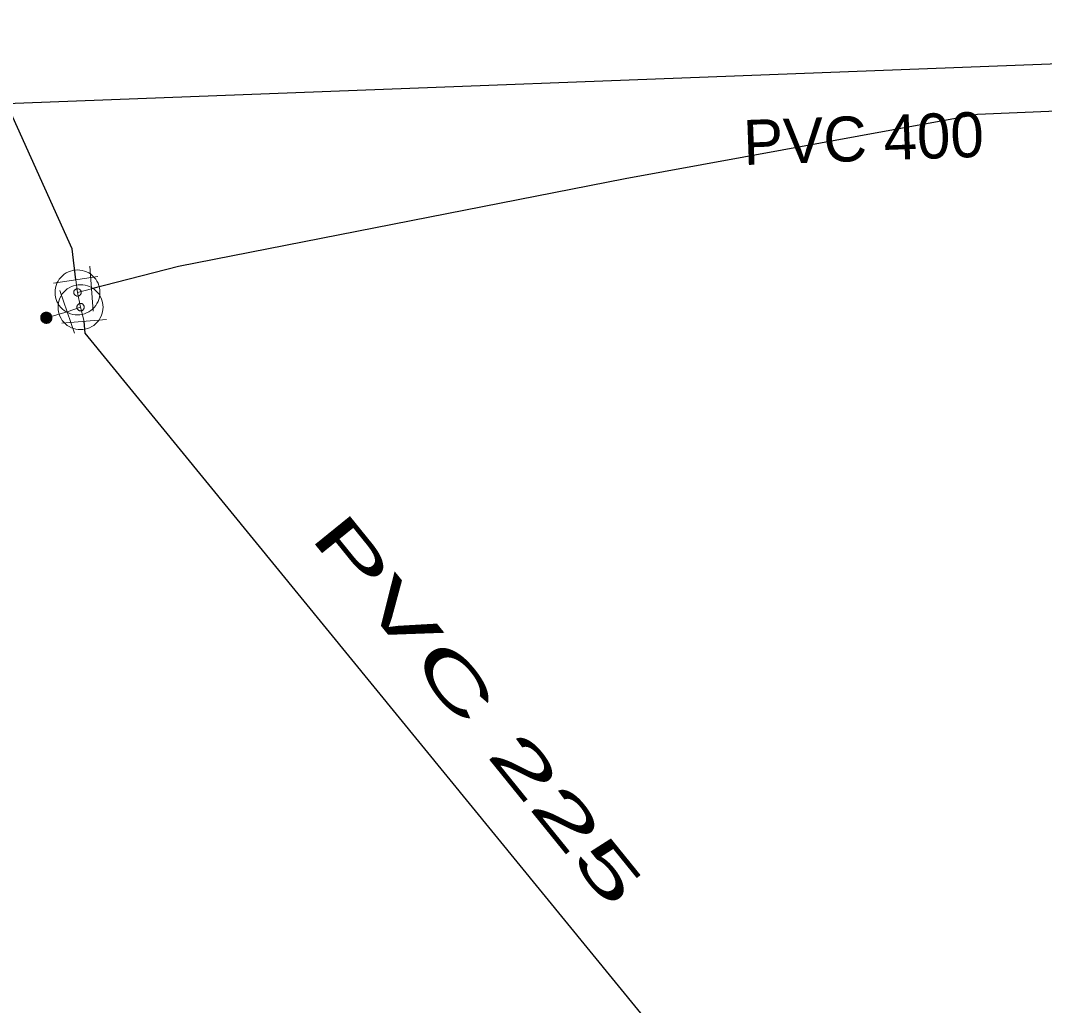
# Model space of a CAD drawing. Extents: x -659250 to -657316, y -997555 to -993684.
# Drawn here: x -658188.9 to -658166.14, y -996468.86 to -996446.96 of the extents above; entities that cross this region are included whole.
import ezdxf

# ---------------------------------------------------------------- set-up
doc = ezdxf.new("R2010")
doc.units = 0
doc.header["$LTSCALE"] = 0.4
doc.layers.add('1', color=7, linetype='Continuous')
for name, color, linetype, lineweight in [('14', 7, 'Continuous', 25), ('17', 7, 'Continuous', 25), ('34', 7, 'Continuous', 13), ('47', 7, 'Continuous', 13), ('9', 7, 'Continuous', 13)]:
    doc.layers.add(name, color=color, linetype=linetype, lineweight=lineweight)

msp = doc.modelspace()

# ---------------------------------------------------------------- linework, layer by layer
at = {"layer": '14'}
msp.add_line((-658148.079, -996447.25), (-658190.719, -996448.87), dxfattribs=at)
at = {"layer": '14', "lineweight": 13}
for p, q in [((-658187.636, -996453.006), (-658187.329, -996452.923)), ((-658187.866, -996453.436), (-658188.329, -996453.569)), ((-658187.57, -996453.333), (-658187.866, -996453.436)), ((-658187.489, -996453.649), (-658187.57, -996453.333))]:
    msp.add_line(p, q, dxfattribs=at)
msp.add_lwpolyline([(-658187.57, -996453.334), (-658187.637, -996453.006), (-658187.677, -996452.73)], dxfattribs=at)
at = {"layer": '17'}
for points in [[(-658187.677, -996452.73), (-658187.756, -996452.037), (-658193.366, -996439.601), (-658202.822, -996415.717), (-658204.513, -996411.723), (-658210.651, -996397.227), (-658216.25, -996384.063), (-658217.364, -996381.052), (-658220.46, -996373.316), (-658223.436, -996366.695), (-658223.489, -996366.02), (-658224.153, -996365.028), (-658230.886, -996355.498), (-658241.289, -996342), (-658242.23, -996340.93)], [(-658056.17, -996447.719), (-658057.34, -996448.37), (-658058.399, -996448.87), (-658072.379, -996455.03), (-658086.712, -996460.184), (-658096.55, -996463.013), (-658107.8, -996460.728), (-658119.059, -996456.26), (-658122.789, -996456.213), (-658137.155, -996451.888), (-658147.859, -996448.16), (-658148.32, -996447.94), (-658149.93, -996448.17), (-658151.399, -996448.37), (-658167.629, -996449.05), (-658175.464, -996450.478), (-658185.39, -996452.43), (-658187.329, -996452.923)], [(-658174.617, -996469.633), (-658187.469, -996453.91), (-658187.489, -996453.649)]]:
    msp.add_lwpolyline(points, dxfattribs=at)
at = {"layer": '34'}
for p, q in [((-658187.29, -996453.421), (-658187.366, -996452.424)), ((-658187.182, -996452.656), (-658188.171, -996452.802)), ((-658188.028, -996452.963), (-658187.704, -996453.909)), ((-658186.99, -996453.61), (-658187.987, -996453.686))]:
    msp.add_line(p, q, dxfattribs=at)
at = {"layer": '47'}
for points in [[(-658187.137, -996453.006), (-658187.14, -996452.954), (-658187.148, -996452.902), (-658187.162, -996452.852), (-658187.179, -996452.803), (-658187.204, -996452.756), (-658187.233, -996452.712), (-658187.266, -996452.672), (-658187.303, -996452.635), (-658187.343, -996452.602), (-658187.387, -996452.573), (-658187.434, -996452.549), (-658187.483, -996452.531), (-658187.532, -996452.517), (-658187.585, -996452.509), (-658187.637, -996452.506), (-658187.689, -996452.509), (-658187.741, -996452.517), (-658187.792, -996452.531), (-658187.84, -996452.549), (-658187.887, -996452.573), (-658187.931, -996452.602), (-658187.972, -996452.635), (-658188.009, -996452.672), (-658188.042, -996452.712), (-658188.07, -996452.756), (-658188.094, -996452.803), (-658188.113, -996452.852), (-658188.125, -996452.902), (-658188.134, -996452.954), (-658188.137, -996453.006), (-658188.134, -996453.058), (-658188.125, -996453.11), (-658188.113, -996453.161), (-658188.094, -996453.209), (-658188.07, -996453.256), (-658188.042, -996453.3), (-658188.009, -996453.341), (-658187.972, -996453.378), (-658187.931, -996453.411), (-658187.887, -996453.439), (-658187.84, -996453.463), (-658187.792, -996453.482), (-658187.741, -996453.495), (-658187.689, -996453.503), (-658187.637, -996453.506), (-658187.585, -996453.503), (-658187.532, -996453.495), (-658187.483, -996453.482), (-658187.434, -996453.463), (-658187.387, -996453.439), (-658187.343, -996453.411), (-658187.303, -996453.378), (-658187.266, -996453.341), (-658187.233, -996453.3), (-658187.204, -996453.256), (-658187.179, -996453.209), (-658187.162, -996453.161), (-658187.148, -996453.11), (-658187.14, -996453.058)], [(-658187.07, -996453.334), (-658187.073, -996453.282), (-658187.081, -996453.23), (-658187.095, -996453.18), (-658187.112, -996453.131), (-658187.137, -996453.084), (-658187.166, -996453.04), (-658187.198, -996453), (-658187.235, -996452.963), (-658187.276, -996452.93), (-658187.32, -996452.901), (-658187.367, -996452.877), (-658187.416, -996452.859), (-658187.465, -996452.845), (-658187.517, -996452.837), (-658187.57, -996452.834), (-658187.622, -996452.837), (-658187.674, -996452.845), (-658187.725, -996452.859), (-658187.772, -996452.877), (-658187.82, -996452.901), (-658187.864, -996452.93), (-658187.904, -996452.963), (-658187.941, -996453), (-658187.975, -996453.04), (-658188.002, -996453.084), (-658188.027, -996453.131), (-658188.046, -996453.18), (-658188.058, -996453.23), (-658188.066, -996453.282), (-658188.07, -996453.334), (-658188.066, -996453.386), (-658188.058, -996453.438), (-658188.046, -996453.489), (-658188.027, -996453.537), (-658188.002, -996453.584), (-658187.975, -996453.628), (-658187.941, -996453.669), (-658187.904, -996453.706), (-658187.864, -996453.739), (-658187.82, -996453.767), (-658187.772, -996453.791), (-658187.725, -996453.81), (-658187.674, -996453.823), (-658187.622, -996453.831), (-658187.57, -996453.834), (-658187.517, -996453.831), (-658187.465, -996453.823), (-658187.416, -996453.81), (-658187.367, -996453.791), (-658187.32, -996453.767), (-658187.276, -996453.739), (-658187.235, -996453.706), (-658187.198, -996453.669), (-658187.166, -996453.628), (-658187.137, -996453.584), (-658187.112, -996453.537), (-658187.095, -996453.489), (-658187.081, -996453.438), (-658187.073, -996453.386)], [(-658187.554, -996453.006), (-658187.554, -996452.997), (-658187.557, -996452.989), (-658187.559, -996452.981), (-658187.562, -996452.973), (-658187.566, -996452.965), (-658187.571, -996452.958), (-658187.576, -996452.951), (-658187.581, -996452.945), (-658187.589, -996452.94), (-658187.596, -996452.935), (-658187.603, -996452.931), (-658187.612, -996452.928), (-658187.62, -996452.926), (-658187.628, -996452.924), (-658187.637, -996452.924), (-658187.646, -996452.924), (-658187.654, -996452.926), (-658187.662, -996452.928), (-658187.67, -996452.931), (-658187.678, -996452.935), (-658187.684, -996452.94), (-658187.692, -996452.945), (-658187.698, -996452.951), (-658187.704, -996452.958), (-658187.708, -996452.965), (-658187.712, -996452.973), (-658187.715, -996452.981), (-658187.717, -996452.989), (-658187.719, -996452.997), (-658187.719, -996453.006), (-658187.719, -996453.015), (-658187.717, -996453.023), (-658187.715, -996453.031), (-658187.712, -996453.039), (-658187.708, -996453.047), (-658187.704, -996453.054), (-658187.698, -996453.061), (-658187.692, -996453.067), (-658187.684, -996453.073), (-658187.678, -996453.077), (-658187.67, -996453.081), (-658187.662, -996453.084), (-658187.654, -996453.086), (-658187.646, -996453.088), (-658187.637, -996453.088), (-658187.628, -996453.088), (-658187.62, -996453.086), (-658187.612, -996453.084), (-658187.603, -996453.081), (-658187.596, -996453.077), (-658187.589, -996453.073), (-658187.581, -996453.067), (-658187.576, -996453.061), (-658187.571, -996453.054), (-658187.566, -996453.047), (-658187.562, -996453.039), (-658187.559, -996453.031), (-658187.557, -996453.023), (-658187.554, -996453.015)], [(-658187.487, -996453.334), (-658187.487, -996453.325), (-658187.49, -996453.317), (-658187.492, -996453.309), (-658187.495, -996453.301), (-658187.499, -996453.293), (-658187.504, -996453.286), (-658187.509, -996453.279), (-658187.514, -996453.273), (-658187.522, -996453.268), (-658187.529, -996453.263), (-658187.536, -996453.259), (-658187.544, -996453.256), (-658187.553, -996453.254), (-658187.561, -996453.252), (-658187.57, -996453.252), (-658187.578, -996453.252), (-658187.587, -996453.254), (-658187.595, -996453.256), (-658187.603, -996453.259), (-658187.61, -996453.263), (-658187.617, -996453.268), (-658187.625, -996453.273), (-658187.63, -996453.279), (-658187.637, -996453.286), (-658187.641, -996453.293), (-658187.644, -996453.301), (-658187.647, -996453.309), (-658187.649, -996453.317), (-658187.652, -996453.325), (-658187.652, -996453.334), (-658187.652, -996453.343), (-658187.649, -996453.351), (-658187.647, -996453.359), (-658187.644, -996453.367), (-658187.641, -996453.375), (-658187.637, -996453.382), (-658187.63, -996453.389), (-658187.625, -996453.395), (-658187.617, -996453.401), (-658187.61, -996453.405), (-658187.603, -996453.409), (-658187.595, -996453.412), (-658187.587, -996453.414), (-658187.578, -996453.416), (-658187.57, -996453.416), (-658187.561, -996453.416), (-658187.553, -996453.414), (-658187.544, -996453.412), (-658187.536, -996453.409), (-658187.529, -996453.405), (-658187.522, -996453.401), (-658187.514, -996453.395), (-658187.509, -996453.389), (-658187.504, -996453.382), (-658187.499, -996453.375), (-658187.495, -996453.367), (-658187.492, -996453.359), (-658187.49, -996453.351), (-658187.487, -996453.343)]]:
    msp.add_lwpolyline(points, close=True, dxfattribs=at)
at = {"layer": '9'}
for points in [[(-658188.455, -996453.569), (-658188.455, -996453.582), (-658188.453, -996453.595), (-658188.45, -996453.608), (-658188.445, -996453.62), (-658188.439, -996453.632), (-658188.432, -996453.643), (-658188.424, -996453.653), (-658188.414, -996453.663), (-658188.404, -996453.671), (-658188.393, -996453.678), (-658188.381, -996453.684), (-658188.369, -996453.689), (-658188.356, -996453.692), (-658188.343, -996453.694), (-658188.33, -996453.696), (-658188.317, -996453.695), (-658188.304, -996453.693), (-658188.291, -996453.69), (-658188.279, -996453.685), (-658188.267, -996453.679), (-658188.256, -996453.672), (-658188.246, -996453.664), (-658188.236, -996453.654), (-658188.228, -996453.644), (-658188.221, -996453.633), (-658188.215, -996453.621), (-658188.21, -996453.609), (-658188.207, -996453.596), (-658188.205, -996453.583), (-658188.203, -996453.57), (-658188.204, -996453.557), (-658188.206, -996453.544), (-658188.209, -996453.531), (-658188.214, -996453.519), (-658188.22, -996453.507), (-658188.227, -996453.496), (-658188.235, -996453.486), (-658188.245, -996453.476), (-658188.255, -996453.468), (-658188.266, -996453.461), (-658188.278, -996453.455), (-658188.29, -996453.45), (-658188.303, -996453.447), (-658188.316, -996453.445), (-658188.329, -996453.444), (-658188.342, -996453.444), (-658188.355, -996453.446), (-658188.368, -996453.449), (-658188.38, -996453.454), (-658188.392, -996453.46), (-658188.403, -996453.467), (-658188.413, -996453.475), (-658188.423, -996453.485), (-658188.431, -996453.495), (-658188.438, -996453.506), (-658188.444, -996453.518), (-658188.449, -996453.53), (-658188.452, -996453.543), (-658188.454, -996453.556)], [(-658188.435, -996453.569), (-658188.436, -996453.58), (-658188.434, -996453.591), (-658188.431, -996453.602), (-658188.427, -996453.612), (-658188.422, -996453.622), (-658188.416, -996453.631), (-658188.409, -996453.64), (-658188.401, -996453.648), (-658188.392, -996453.655), (-658188.383, -996453.661), (-658188.373, -996453.666), (-658188.363, -996453.67), (-658188.352, -996453.673), (-658188.341, -996453.676), (-658188.33, -996453.676), (-658188.319, -996453.676), (-658188.308, -996453.674), (-658188.297, -996453.671), (-658188.287, -996453.667), (-658188.277, -996453.662), (-658188.268, -996453.656), (-658188.259, -996453.649), (-658188.251, -996453.641), (-658188.244, -996453.632), (-658188.238, -996453.623), (-658188.233, -996453.613), (-658188.229, -996453.603), (-658188.226, -996453.592), (-658188.224, -996453.581), (-658188.223, -996453.57), (-658188.223, -996453.559), (-658188.225, -996453.548), (-658188.228, -996453.537), (-658188.232, -996453.527), (-658188.237, -996453.517), (-658188.243, -996453.508), (-658188.25, -996453.499), (-658188.258, -996453.491), (-658188.267, -996453.484), (-658188.276, -996453.478), (-658188.286, -996453.473), (-658188.296, -996453.469), (-658188.307, -996453.466), (-658188.318, -996453.464), (-658188.329, -996453.464), (-658188.34, -996453.463), (-658188.351, -996453.465), (-658188.362, -996453.468), (-658188.372, -996453.472), (-658188.382, -996453.477), (-658188.391, -996453.483), (-658188.4, -996453.49), (-658188.408, -996453.498), (-658188.415, -996453.507), (-658188.421, -996453.516), (-658188.426, -996453.526), (-658188.43, -996453.536), (-658188.433, -996453.547), (-658188.435, -996453.558)], [(-658188.416, -996453.569), (-658188.416, -996453.578), (-658188.415, -996453.587), (-658188.412, -996453.596), (-658188.409, -996453.604), (-658188.405, -996453.612), (-658188.4, -996453.62), (-658188.394, -996453.627), (-658188.388, -996453.633), (-658188.381, -996453.639), (-658188.373, -996453.644), (-658188.365, -996453.648), (-658188.357, -996453.651), (-658188.348, -996453.654), (-658188.339, -996453.655), (-658188.33, -996453.657), (-658188.321, -996453.656), (-658188.312, -996453.655), (-658188.303, -996453.652), (-658188.295, -996453.649), (-658188.287, -996453.645), (-658188.279, -996453.64), (-658188.272, -996453.634), (-658188.266, -996453.628), (-658188.26, -996453.621), (-658188.255, -996453.613), (-658188.251, -996453.605), (-658188.248, -996453.597), (-658188.245, -996453.588), (-658188.244, -996453.579), (-658188.242, -996453.57), (-658188.243, -996453.561), (-658188.244, -996453.552), (-658188.247, -996453.543), (-658188.25, -996453.535), (-658188.254, -996453.527), (-658188.259, -996453.519), (-658188.265, -996453.512), (-658188.271, -996453.506), (-658188.278, -996453.5), (-658188.286, -996453.495), (-658188.294, -996453.491), (-658188.302, -996453.488), (-658188.311, -996453.485), (-658188.32, -996453.484), (-658188.329, -996453.483), (-658188.338, -996453.483), (-658188.347, -996453.484), (-658188.356, -996453.487), (-658188.364, -996453.49), (-658188.372, -996453.494), (-658188.38, -996453.499), (-658188.387, -996453.505), (-658188.393, -996453.511), (-658188.399, -996453.518), (-658188.404, -996453.526), (-658188.408, -996453.534), (-658188.411, -996453.542), (-658188.414, -996453.551), (-658188.415, -996453.56)], [(-658188.396, -996453.569), (-658188.396, -996453.576), (-658188.395, -996453.583), (-658188.394, -996453.59), (-658188.391, -996453.596), (-658188.388, -996453.602), (-658188.384, -996453.608), (-658188.38, -996453.614), (-658188.375, -996453.619), (-658188.369, -996453.623), (-658188.363, -996453.627), (-658188.357, -996453.63), (-658188.351, -996453.633), (-658188.344, -996453.634), (-658188.337, -996453.637), (-658188.33, -996453.637), (-658188.323, -996453.637), (-658188.316, -996453.635), (-658188.309, -996453.634), (-658188.303, -996453.631), (-658188.296, -996453.628), (-658188.291, -996453.624), (-658188.285, -996453.62), (-658188.28, -996453.615), (-658188.276, -996453.609), (-658188.272, -996453.603), (-658188.269, -996453.597), (-658188.266, -996453.591), (-658188.264, -996453.584), (-658188.263, -996453.577), (-658188.262, -996453.57), (-658188.262, -996453.563), (-658188.263, -996453.556), (-658188.265, -996453.549), (-658188.268, -996453.543), (-658188.271, -996453.536), (-658188.275, -996453.531), (-658188.279, -996453.525), (-658188.284, -996453.52), (-658188.29, -996453.516), (-658188.295, -996453.512), (-658188.302, -996453.509), (-658188.308, -996453.506), (-658188.315, -996453.504), (-658188.322, -996453.503), (-658188.329, -996453.503), (-658188.336, -996453.503), (-658188.343, -996453.503), (-658188.35, -996453.505), (-658188.356, -996453.508), (-658188.362, -996453.511), (-658188.368, -996453.515), (-658188.374, -996453.519), (-658188.379, -996453.524), (-658188.383, -996453.53), (-658188.387, -996453.535), (-658188.39, -996453.542), (-658188.393, -996453.548), (-658188.394, -996453.555), (-658188.396, -996453.562)], [(-658188.376, -996453.569), (-658188.376, -996453.574), (-658188.376, -996453.579), (-658188.375, -996453.584), (-658188.373, -996453.588), (-658188.371, -996453.593), (-658188.368, -996453.597), (-658188.365, -996453.6), (-658188.361, -996453.604), (-658188.358, -996453.607), (-658188.354, -996453.61), (-658188.349, -996453.612), (-658188.345, -996453.614), (-658188.34, -996453.615), (-658188.335, -996453.617), (-658188.33, -996453.617), (-658188.325, -996453.617), (-658188.32, -996453.616), (-658188.315, -996453.615), (-658188.311, -996453.613), (-658188.306, -996453.611), (-658188.302, -996453.608), (-658188.298, -996453.605), (-658188.295, -996453.601), (-658188.292, -996453.598), (-658188.289, -996453.594), (-658188.287, -996453.589), (-658188.285, -996453.585), (-658188.284, -996453.58), (-658188.283, -996453.575), (-658188.282, -996453.57), (-658188.282, -996453.565), (-658188.283, -996453.56), (-658188.284, -996453.555), (-658188.286, -996453.551), (-658188.288, -996453.546), (-658188.291, -996453.542), (-658188.294, -996453.538), (-658188.297, -996453.535), (-658188.301, -996453.532), (-658188.305, -996453.529), (-658188.31, -996453.527), (-658188.314, -996453.525), (-658188.319, -996453.524), (-658188.324, -996453.523), (-658188.329, -996453.523), (-658188.334, -996453.523), (-658188.339, -996453.524), (-658188.344, -996453.524), (-658188.348, -996453.526), (-658188.353, -996453.528), (-658188.357, -996453.531), (-658188.36, -996453.534), (-658188.364, -996453.537), (-658188.367, -996453.541), (-658188.37, -996453.545), (-658188.372, -996453.55), (-658188.374, -996453.554), (-658188.375, -996453.559), (-658188.376, -996453.564)], [(-658188.356, -996453.569), (-658188.356, -996453.572), (-658188.357, -996453.575), (-658188.356, -996453.577), (-658188.355, -996453.58), (-658188.354, -996453.583), (-658188.352, -996453.585), (-658188.35, -996453.587), (-658188.348, -996453.589), (-658188.346, -996453.591), (-658188.344, -996453.593), (-658188.341, -996453.595), (-658188.338, -996453.596), (-658188.336, -996453.596), (-658188.333, -996453.597), (-658188.33, -996453.597), (-658188.327, -996453.597), (-658188.324, -996453.597), (-658188.321, -996453.596), (-658188.319, -996453.595), (-658188.316, -996453.594), (-658188.314, -996453.592), (-658188.311, -996453.59), (-658188.309, -996453.588), (-658188.308, -996453.586), (-658188.306, -996453.584), (-658188.305, -996453.581), (-658188.303, -996453.578), (-658188.303, -996453.576), (-658188.302, -996453.573), (-658188.301, -996453.57), (-658188.302, -996453.567), (-658188.302, -996453.564), (-658188.303, -996453.561), (-658188.304, -996453.559), (-658188.305, -996453.556), (-658188.307, -996453.554), (-658188.308, -996453.551), (-658188.31, -996453.549), (-658188.313, -996453.548), (-658188.315, -996453.546), (-658188.318, -996453.545), (-658188.32, -996453.544), (-658188.323, -996453.543), (-658188.326, -996453.543), (-658188.329, -996453.542), (-658188.332, -996453.543), (-658188.335, -996453.542), (-658188.337, -996453.544), (-658188.34, -996453.544), (-658188.343, -996453.545), (-658188.345, -996453.547), (-658188.347, -996453.548), (-658188.349, -996453.55), (-658188.351, -996453.553), (-658188.353, -996453.555), (-658188.354, -996453.558), (-658188.355, -996453.56), (-658188.356, -996453.563), (-658188.356, -996453.566)], [(-658188.337, -996453.569), (-658188.337, -996453.571), (-658188.337, -996453.571), (-658188.336, -996453.571), (-658188.336, -996453.573), (-658188.337, -996453.574), (-658188.335, -996453.574), (-658188.335, -996453.574), (-658188.335, -996453.576), (-658188.335, -996453.576), (-658188.334, -996453.577), (-658188.332, -996453.577), (-658188.332, -996453.577), (-658188.332, -996453.578), (-658188.33, -996453.578), (-658188.33, -996453.578), (-658188.329, -996453.578), (-658188.328, -996453.578), (-658188.328, -996453.577), (-658188.327, -996453.577), (-658188.325, -996453.577), (-658188.325, -996453.576), (-658188.325, -996453.576), (-658188.324, -996453.575), (-658188.324, -996453.575), (-658188.322, -996453.574), (-658188.322, -996453.573), (-658188.321, -996453.572), (-658188.321, -996453.572), (-658188.321, -996453.571), (-658188.321, -996453.57), (-658188.321, -996453.569), (-658188.321, -996453.568), (-658188.321, -996453.568), (-658188.322, -996453.567), (-658188.322, -996453.566), (-658188.323, -996453.565), (-658188.323, -996453.565), (-658188.324, -996453.564), (-658188.324, -996453.564), (-658188.325, -996453.563), (-658188.326, -996453.563), (-658188.327, -996453.562), (-658188.327, -996453.562), (-658188.328, -996453.562), (-658188.329, -996453.562), (-658188.33, -996453.562), (-658188.331, -996453.562), (-658188.331, -996453.562), (-658188.332, -996453.563), (-658188.333, -996453.562), (-658188.334, -996453.564), (-658188.334, -996453.564), (-658188.335, -996453.564), (-658188.335, -996453.564), (-658188.336, -996453.566), (-658188.336, -996453.567), (-658188.336, -996453.568), (-658188.337, -996453.568), (-658188.337, -996453.569)]]:
    msp.add_lwpolyline(points, close=True, dxfattribs=at)

# ---------------------------------------------------------------- texts
at = {"layer": '1'}
msp.add_text('PVC 400 ', height=1, rotation=2, dxfattribs=at).set_placement((-658172.821, -996450.176))
at = {"layer": '1', "width": 2}
msp.add_text('PVC 225 ', height=1, rotation=309, dxfattribs=at).set_placement((-658182.495, -996458.437))

doc.saveas('drawing.dxf')
